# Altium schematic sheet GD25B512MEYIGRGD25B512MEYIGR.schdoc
size 127 x 101 mm
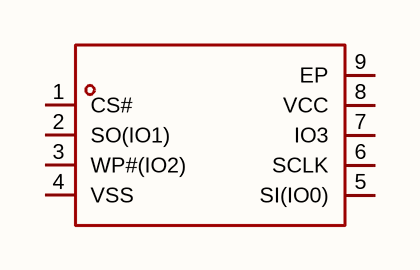
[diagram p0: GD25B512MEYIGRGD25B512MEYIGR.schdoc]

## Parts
U?  gd25b512meyigr  [WSON-8_L8.0-W6.0-P1.27-TL-EP-1]  (value not drawn)

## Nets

Not connected (* = marked no-connect by the designer): U? 1(CS#) 2(SO(IO1)) 3(WP#(IO2)) 4(VSS) 5(SI(IO0)) 6(SCLK) 7(IO3) 8(VCC) 9(EP)

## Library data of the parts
U? = gd25b512meyigr: 接口类型:SPI;存储容量:512Mbit;时钟频率(fc):133MHz;; Manufacturer: GigaDevice(兆易创新); AddInBom: yes; ModelId: 9b0b95cb42c44ddaa75bcc393c15d437; ModelTransform: 314.96,236.22,0,0,0,0,0,0,0; Interface: SPI; Clock Frequency: 133MHz; Voltage - Supply: 2.7V~3.6V; Standby Supply Current: 16uA; Program / Erase Cycles: 100000次; Page Programming Time (Tpp): 150us; Data Retention - TDR (Year): 20年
